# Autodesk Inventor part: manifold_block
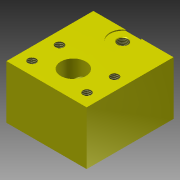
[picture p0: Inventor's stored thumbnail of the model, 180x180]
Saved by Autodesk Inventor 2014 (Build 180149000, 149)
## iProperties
Created: 2006-02
Part Number: manifold_block
Document SubType Name: Modeling
Designer: C Bull
Manufacturer: Standard
Standards Organization: Custom
Material: SAE 1020
Mass: 3910.59 g
Surface Area: 647.837 cm^2
Volume: 497.53 cm^3
Density: 7.86 g/cm^3
Appearance: Smooth - Yellow
RuleStatus: InUse
Author: C Bull
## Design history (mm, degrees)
sketch "Sketch2"
  geometry: L1 (38.1, -41.275)-(-38.1, -41.275); L2 (-38.1, -41.275)-(-38.1, 41.275); L3 (-38.1, 41.275)-(38.1, 41.275); L4 (38.1, 41.275)-(38.1, -41.275); L5 (-26.162, -28.956)-(26.162, -2.794); 7 further points
  constraints: 10 end point, 3 horizontal alignment, 3 midpoint, 3 vertical alignment, 2 parallel, 1 coincident, 1 horizontal, 1 perpendicular
  dimensions: "block_height" = 82.55 distance of L3.end L1.start; "block_width" = 76.2 distance of L1.start L1.end; "port_a_vert_offset" = 57.15 distance from line of point (0, -15.875) L3; "port_a_hor_offset" = 38.1 distance from line of point (0, -15.875) L4; "port_a_x_dist_between_screw" = 52.324 distance of L5.end point (-26.162, -2.794); "port_a_y_dist_between_screw" = 26.162 distance of L5.end point (26.162, -28.956)
extrude "Extrusion1" new body sketch "Sketch2" taper "d8" = 0 deg; distance "block_depth" = 50.8
hole "Port_A" sketch "Sketch2" diameter "port_a_port_dia" = 23.876; stored, may be unused: countersink angle "d13" = 90 deg, drill point angle "port_a_drill_tip_angle" = 118 deg; dims "d10" = 6, "d11" = 4, "d12" = 2, "port_a_d_d" = 25.4 (derived)
hole "Port_A_Threads" sketch "Sketch2" diameter "d16" = 7.7978; stored, may be unused: countersink angle "d20" = 90 deg, drill point angle "d22" = 118 deg; dims "d17" = 6, "d18" = 4, "d19" = 2, "d21" = 12.827 (derived)
sketch "Sketch3"
  geometry: L1 (38.1, -42.357)-(38.1, 40.193) reference; 1 further point
  dimensions: "SAE_Port" = 38.1 distance from line of point (0, 30.193) L1 (= port_a_hor_offset); "d24" = 10 vertical distance of point (0, 30.193) L1.end
feature "iFeature7:1" sketch "Sketch3"
sketch "Sketch4"
  geometry: L1 (76.2, -50.8)-(76.2, 0) reference; L2 (11.938, -38.481)-(64.262, -12.319); 5 further points
  constraints: 2 end point, 2 horizontal alignment, 2 vertical alignment, 1 coincident, 1 midpoint
  dimensions: "port_c_hor_offset" = 38.1 distance from line of point (38.1, -25.4) L1; "port_c_depth_from_front" = 25.4 vertical distance of point (38.1, -25.4) L1.start; "port_c_x_dist_between_screw" = 52.324 distance of point (64.262, -38.481) L2.start; "port_c_y_dist_between_screw" = 26.162 distance of L2.end point (64.262, -38.481)
hole "Port_C" sketch "Sketch4" diameter "port_c_port_dia" = 23.876; stored, may be unused: countersink angle "d33" = 90 deg, drill point angle "port_c_drill_tip_angle" = 118 deg; dims "d30" = 6, "d31" = 4, "d32" = 2, "port_c_vert_offset" = 57.15
hole "Port_C_Threads" sketch "Sketch4" diameter "d36" = 7.7978; stored, may be unused: countersink angle "d40" = 90 deg, drill point angle "d42" = 118 deg; dims "d37" = 6, "d38" = 4, "d39" = 2, "d41" = 12.827 (derived)
sketch "Sketch5"
  geometry: L1 (38.1, 41.275)-(38.1, -41.275) reference; L2 (38.1, -41.275)-(-38.1, -41.275) reference; L3 (26.162, 2.794)-(-26.162, 28.956); 4 further points
  constraints: 2 end point, 2 horizontal alignment, 2 vertical alignment, 1 coincident, 1 midpoint
  dimensions: "port_b_x_dist_between_screw" = 52.324 distance of L3.start point (-26.162, 2.794); "port_b_y_dist_between_screw" = 26.162 distance of point (26.162, 28.956) L3.start; "port_b_vert_offset" = 57.15 distance from line of point (0, 15.875) L2; "port_b_hor_offset" = 38.1 distance from line of L1 point (0, 15.875)
hole "Port_B" sketch "Sketch5" diameter "port_b_port_dia" = 23.876; stored, may be unused: countersink angle "d51" = 82 deg, drill point angle "d53" = 118 deg; dims "d48" = 12.7, "d49" = 9.525, "d50" = 6.35, "port_b_d_d" = 25.4 (= 0.5 x block_depth)
hole "Port_B_Threads" sketch "Sketch5" diameter "d54" = 7.7978; stored, may be unused: countersink angle "d58" = 82 deg, drill point angle "d60" = 118 deg; dims "d55" = 12.7, "d56" = 9.525, "d57" = 6.35, "d59" = 12.827 (derived)
body "Solid1"
other parameters: "tap_dim" = 7.9375 [user parameter], "weight" = 13.83457 [user parameter], "working_press" = 3445000 [user parameter], "AA_SAE_dim" = 23.876 [user parameter], "Port_A_Drill_Depth" = 12.827 [user parameter], "Port_B_Drill_Depth" = 12.827 [user parameter], "Port_C_Drill_Depth" = 12.827 [user parameter]
